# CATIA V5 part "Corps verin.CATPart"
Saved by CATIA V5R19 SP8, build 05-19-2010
Part number: Corps verin
Publications: "Diamètre interne verin"
Bounding box of the stored display mesh (mm): x -150 to 150, y -125 to 1500, z -149.807 to 380
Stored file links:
  C:\Users\rcousturie\Desktop\EU_thinkMotion\iao\IAO_MMS_Groupe1\flacan\flacan\flacan\Corps verin.CATPart
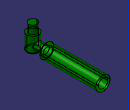
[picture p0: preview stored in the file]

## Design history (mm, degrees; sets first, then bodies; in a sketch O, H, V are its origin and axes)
Parameters
  `Diamètre interne verin` = 200 mm
Body1 (main body)
  Sketch1 on xy-plane, origin (0, 0, 0), H (1, 0, 0), V (0, 1, 0)
    circle A1 centre (0, 0) radius 125
    point P1 (0, 0)
    radius A1 = 125
    distance O P1 = 0
  Pad1: profile Sketch1, direction (0, 0, 1), length 205, opposite side length 125
  Sketch2 on end face of Pad1, origin (0, 0, 205), H (1, 0, 0), V (0, 1, 0)
    circle A1 centre (0, 0) radius 87.5
    point P1 (0, 0)
    radius A1 = 87.5
    distance P1 O = 0
  Pad2: profile Sketch2, direction (0, 0, 1), length 175
  Sketch3 on zx-plane, origin (0, 0, 0), H (-1, 0, 0), V (0, 0, 1)
    circle A1 centre (0, 0) radius 87.5
    radius A1 = 87.5
  Pad3: profile Sketch3, direction (0, 1, 0), length 300
  Sketch4 on end face of Pad3, origin (0, 300, 0), H (-1, 0, 0), V (0, 0, 1)
    circle A1 centre (0, 0) radius 150
    radius A1 = 150
  Pad4: profile Sketch4, direction (0, 1, 0), length 1200
  Sketch5 on end face of Pad4, origin (0, 1500, 0), H (-1, 0, 0), V (0, 0, 1)
    circle A1 centre (0, 0) radius 100
    radius A1 = 100 {= `Diamètre interne verin` /2}
  Pocket1: profile Sketch5, direction (0, -1, 0), length 1175
  Chamfer1: length 35, angle 60, on edge [face of Pad3 from Sketch3.A1 | start face of Pad4]
  Chamfer2: length 10, angle 60, on edge [start face of Pad1 | face of Pad1 from Sketch1.A1]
